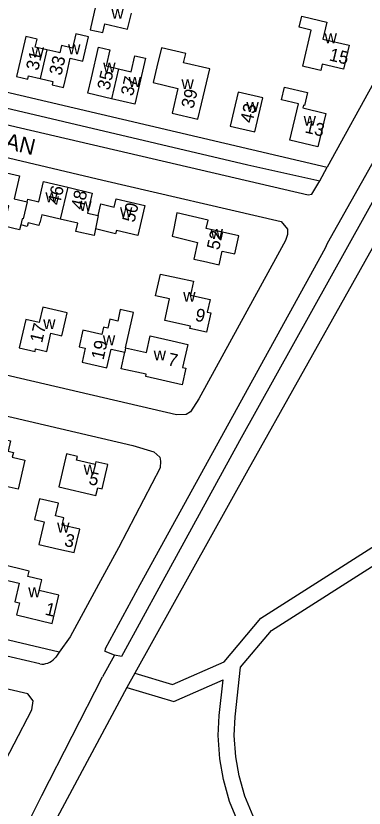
# Model space of a CAD drawing. Extents: x 161773 to 163836, y 384796 to 386521.
# Drawn here: x 162613.8 to 162722.6, y 385630.2 to 385877.5 of the extents above; entities that cross this region are included whole.
import ezdxf

# ---------------------------------------------------------------- set-up
doc = ezdxf.new("R2010")
doc.units = 0
for name, color, linetype in [('BLT_Basislijn', 7, 'Continuous'), ('BLT_Bebouwing', 7, 'Continuous'), ('BLT_Centroide', 7, 'Continuous'), ('BLT_Huisnummer', 7, 'Continuous'), ('BLT_Huisnummer_ tussenligend', 7, 'Continuous'), ('BLT_Onderverdeling_panden', 7, 'Continuous'), ('BLT_Straatnaam', 7, 'Continuous')]:
    doc.layers.add(name, color=color, linetype=linetype)

msp = doc.modelspace()

# ---------------------------------------------------------------- linework, layer by layer
at = {"layer": 'BLT_Basislijn'}
for p, q in [((162708.69, 385825.93), (162711.04, 385830.23)), ((162630.76, 385683.64), (162627.38, 385678.91)), ((162627.38, 385678.91), (162626.29, 385677.38)), ((162644.59, 385677.96), (162640.89, 385671.23)), ((162621.96, 385634.13), (162640.89, 385671.23)), ((162648.46, 385667.88), (162618.75, 385612.62)), ((162609.1, 385608.91), (162621.96, 385634.13))]:
    msp.add_line(p, q, dxfattribs=at)
for points in [[(162644.59, 385677.96), (162641.67, 385679.15), (162641.76, 385680.04), (162652.61, 385700), (162710.55, 385805.08), (162711.1, 385806.51), (162756.83, 385887.63), (162796.99, 385960.06), (162856.89, 386059.07)], [(162861.67, 386056.19), (162795.28, 385945.23), (162766.85, 385893.4), (162734.28, 385835.66), (162683.66, 385744.84), (162659.11, 385700), (162646.79, 385677.52), (162644.59, 385677.96)], [(162533.46, 385940.28), (162600, 385924.77), (162684.08, 385905.17), (162740.53, 385892.3), (162742.38, 385890.58), (162742.44, 385887.3), (162711.04, 385830.23)], [(162521.74, 385882.16), (162520.32, 385875.52), (162600, 385856.24), (162711.04, 385830.23)], [(162497.15, 385875.44), (162497.39, 385872.99), (162499.99, 385869.75), (162501.74, 385869), (162512.55, 385866.3), (162600, 385846.01), (162705.04, 385821.65), (162706.25, 385821.76), (162708.69, 385825.93)], [(162497.15, 385875.44), (162600, 385851.25), (162686.26, 385830.96), (162708.69, 385825.93)], [(162506.71, 385857.98), (162600, 385835.85), (162640.95, 385826.14), (162696.67, 385813.29), (162698.68, 385810.91), (162698.59, 385809.21), (162697.98, 385807.33), (162695.51, 385802.74), (162670.9, 385757.98), (162668.34, 385753.87), (162666.97, 385753.1), (162663.98, 385752.9), (162600, 385767.81), (162494.17, 385792.47), (162493.82, 385792.55)], [(162741.56, 385834.36), (162735.26, 385823.07), (162686.29, 385735.67), (162650.94, 385672.36)], [(162678.87, 385675.87), (162690.27, 385689.5), (162799.69, 385759.13), (162858.66, 385788.41)], [(162743.64, 385587.62), (162731.85, 385595.69), (162725.41, 385596.94), (162718, 385599.35), (162710.34, 385603.22), (162703.55, 385608.09), (162700.18, 385610.97), (162695.05, 385616.61), (162691.69, 385621.09), (162687.87, 385627.7), (162685.3, 385633.96), (162683.54, 385640.26), (162682.52, 385646.23), (162681.95, 385652.91), (162682.29, 385658.69), (162684, 385674.21), (162693.61, 385685.7), (162802.16, 385754.77), (162860.4, 385783.7)], [(162491.31, 385780.26), (162492.03, 385780.09), (162600, 385755.09), (162650.39, 385743.43), (162656.88, 385741.42), (162658.73, 385739.77), (162658.98, 385738.52), (162658.89, 385736.42), (162645.84, 385711.4), (162639.64, 385700), (162630.76, 385683.64)], [(162627.38, 385678.91), (162600, 385685.3), (162537.03, 385700), (162487.65, 385711.18), (162478.88, 385713.69)], [(162621.27, 385675.2), (162598.86, 385680.43), (162535.91, 385695.13), (162486.41, 385706.33), (162469.09, 385711.3)], [(162607.61, 385639.65), (162618.82, 385660.94), (162619.18, 385663.66), (162617.56, 385665.85), (162600, 385669.93), (162562.75, 385678.57), (162562.34, 385678.67)], [(162621.27, 385675.2), (162621.92, 385675.16), (162622.57, 385675.19), (162623.21, 385675.31), (162623.84, 385675.5), (162624.43, 385675.77), (162624.99, 385676.1), (162625.51, 385676.51), (162625.96, 385676.97), (162626.29, 385677.38)], [(162650.94, 385672.36), (162662.77, 385668.84), (162678.87, 385675.87)], [(162650.94, 385672.36), (162648.46, 385667.88)], [(162648.46, 385667.88), (162663.1, 385663.53), (162678.54, 385670.27)], [(162741.95, 385582.71), (162729.88, 385590.98), (162724.16, 385592.09), (162716.09, 385594.71), (162707.74, 385598.93), (162700.47, 385604.15), (162696.69, 385607.37), (162691.19, 385613.42), (162687.52, 385618.33), (162683.37, 385625.49), (162680.56, 385632.34), (162678.66, 385639.16), (162677.55, 385645.59), (162676.94, 385652.85), (162677.31, 385659.12), (162678.54, 385670.27)]]:
    msp.add_lwpolyline(points, dxfattribs=at)
at = {"layer": 'BLT_Bebouwing'}
for points in [[(162638.83, 385880.92), (162637.03, 385873.14)], [(162637.03, 385873.14), (162640.96, 385872.21), (162641.62, 385874.99), (162648.72, 385873.32), (162649.9, 385878.32)], [(162706.09, 385876.67), (162710.96, 385875.52), (162709.72, 385870.21), (162717.94, 385868.28), (162716.09, 385860.86), (162709.47, 385862.42), (162709, 385860.43), (162704.13, 385861.58), (162703.42, 385861.74), (162706.07, 385872.99), (162702.33, 385873.87), (162703.15, 385877.36), (162706.09, 385876.67)], [(162623.53, 385866.87), (162619.87, 385867.73), (162620.45, 385870.16), (162616.92, 385870.99), (162615.13, 385863.39), (162613.99, 385858.52), (162617.56, 385857.68), (162617.81, 385858.74), (162621.42, 385857.89)], [(162621.42, 385857.89), (162625.38, 385856.95), (162625.13, 385855.88), (162628.67, 385855.05), (162629.81, 385859.91), (162630.82, 385864.21), (162634.71, 385863.3), (162636.51, 385870.94)], [(162636.51, 385870.94), (162632.57, 385871.87), (162631.49, 385867.36), (162628.07, 385868.17), (162627.54, 385865.92), (162627.18, 385866.01), (162623.53, 385866.87)], [(162643.72, 385851.55), (162636.28, 385853.28), (162637.41, 385858.15), (162639.62, 385867.68), (162643.15, 385866.86), (162641.98, 385861.84), (162645.89, 385860.94)], [(162671.76, 385850.03), (162674.36, 385860.87), (162666.21, 385862.82), (162666.9, 385865.69), (162659.27, 385867.52), (162657.83, 385861.5), (162656.66, 385856.64), (162664.43, 385854.77), (162662.59, 385847.08), (162670.59, 385845.17), (162671.76, 385850.03)], [(162645.89, 385860.94), (162649.8, 385860.03), (162650.95, 385865), (162654.3, 385864.22), (162652.1, 385854.74), (162650.97, 385849.87), (162643.72, 385851.55)], [(162688.44, 385841.22), (162690.93, 385851.86), (162683.19, 385853.67), (162681.84, 385847.91), (162680.7, 385843.04), (162688.44, 385841.22)], [(162710.56, 385846.97), (162708.15, 385836.61), (162699.36, 385838.65), (162702.11, 385850.04), (162696.78, 385851.27), (162697.7, 385855.24), (162704.91, 385853.58), (162703.97, 385849.52), (162703.6, 385849.61), (162703.4, 385848.74), (162710.56, 385846.97)], [(162607.7, 385829.23), (162615, 385827.52), (162613.33, 385820.39), (162617.39, 385819.43)], [(162617.39, 385819.43), (162617.59, 385820.25), (162620.96, 385819.46), (162622.43, 385825.73), (162630.02, 385823.95)], [(162630.02, 385823.95), (162637.62, 385822.17), (162636.15, 385815.9), (162639.52, 385815.11)], [(162615.34, 385812.19), (162615, 385810.71), (162610.12, 385811.86), (162611.61, 385818.18), (162605.44, 385819.63)], [(162639.52, 385815.11), (162640.38, 385818.77), (162644.49, 385817.8), (162645.1, 385820.39), (162654.09, 385818.28), (162652.95, 385813.41), (162651.88, 385808.89), (162645.19, 385810.46), (162644.96, 385809.48), (162638.7, 385810.94)], [(162669.35, 385801.57), (162672.41, 385800.87), (162677.28, 385799.77), (162678.25, 385804.05), (162682.15, 385803.16), (162683.43, 385808.79), (162673.25, 385811.1), (162673.85, 385813.74), (162664.1, 385815.95), (162663.12, 385811.05), (162662.64, 385808.68), (162670.52, 385806.76), (162669.35, 385801.57)], [(162627.69, 385814.01), (162621.9, 385815.37), (162621.31, 385812.86), (162621.16, 385812.9), (162620.96, 385812.08), (162617.65, 385812.86), (162617.38, 385811.71), (162615.34, 385812.19)], [(162638.7, 385810.94), (162638.22, 385808.88), (162632.54, 385810.21), (162633.14, 385812.73), (162627.69, 385814.01)], [(162664.38, 385795.67), (162669.27, 385794.61), (162668.33, 385790.34), (162674.47, 385788.99), (162673.59, 385785), (162674.68, 385784.76), (162673.35, 385778.71), (162668.16, 385779.87), (162668.32, 385780.64), (162660.32, 385782.41), (162661.81, 385789.16), (162657.44, 385790.12), (162658.93, 385796.89), (162664.38, 385795.67)], [(162629.28, 385782.49), (162629.8, 385784.78), (162622.2, 385786.53), (162621.1, 385781.75), (162616.92, 385782.71), (162616.01, 385778.74), (162614.89, 385773.86), (162619.79, 385772.74), (162619.97, 385773.52), (162623.44, 385772.72), (162624.75, 385778.4), (162628.16, 385777.62), (162629.28, 385782.49)], [(162648.08, 385773.82), (162650.56, 385784.86), (162646.42, 385785.79), (162645.61, 385782.22), (162643.18, 385782.76), (162642.57, 385780.04), (162641.16, 385780.35), (162640.64, 385778.02), (162634.73, 385779.35), (162633.57, 385774.17), (162635.47, 385773.74), (162634.48, 385769.34), (162642.21, 385767.61), (162643.53, 385773.46), (162647.86, 385772.49)], [(162648.08, 385773.82), (162654.57, 385772.36), (162655.76, 385777.6), (162662.65, 385776.04), (162667.53, 385774.93), (162665.89, 385767.7), (162666.91, 385767.47), (162665.73, 385762.29), (162654.35, 385764.87), (162654.52, 385765.62), (162646.7, 385767.32), (162647.86, 385772.49)], [(162604.82, 385746.48), (162612.13, 385744.8), (162611.39, 385741.6), (162613.03, 385741.23), (162612.69, 385739.76), (162616.63, 385738.85), (162614.52, 385729.71), (162608.87, 385731.02), (162609.8, 385734.73), (162602.5, 385736.42)], [(162633.04, 385739.96), (162629.64, 385740.74), (162627.26, 385730.47), (162638.81, 385727.79), (162639.37, 385730.19), (162640.8, 385729.86), (162642.56, 385737.44), (162638.77, 385738.32), (162638.56, 385737.44), (162632.77, 385738.78), (162633.04, 385739.96)], [(162627.18, 385711.07), (162632.05, 385709.94), (162633.75, 385717.25), (162628.28, 385718.52), (162628.81, 385720.78), (162626.19, 385721.39), (162627.12, 385725.35), (162621.17, 385726.74), (162619.68, 385720.3), (162622.64, 385719.61), (162620.99, 385712.51), (162627.18, 385711.07)], [(162621.1, 385698.16), (162621.89, 385701.47), (162617.58, 385702.5), (162617.98, 385704.2), (162609.15, 385706.31), (162608.11, 385701.96), (162614.84, 385700.41), (162613.51, 385694.63), (162614.9, 385694.31), (162613.96, 385690.49), (162625.12, 385687.84), (162627.23, 385696.7), (162621.1, 385698.16)]]:
    msp.add_lwpolyline(points, dxfattribs=at)
at = {"layer": 'BLT_Onderverdeling_panden'}
for p, q in [((162623.53, 385866.87), (162621.42, 385857.89)), ((162645.89, 385860.94), (162643.72, 385851.55)), ((162630.02, 385823.95), (162627.69, 385814.01)), ((162639.52, 385815.11), (162638.7, 385810.94)), ((162648.08, 385773.82), (162647.86, 385772.49))]:
    msp.add_line(p, q, dxfattribs=at)
msp.add_lwpolyline([(162617.39, 385819.43), (162616.14, 385814.07), (162615.8, 385814.15), (162615.34, 385812.19)], dxfattribs=at)

# ---------------------------------------------------------------- texts
at = {"layer": 'BLT_Centroide'}
for p in [(162643.65, 385876.56), (162710.21, 385868.91), (162630.12, 385865.44), (162618.75, 385864.53), (162641.09, 385859.75), (162649.02, 385855.28), (162665.52, 385854.59), (162685.81, 385847.45), (162703.67, 385843.17), (162623.06, 385819.28), (162633.61, 385816.55), (162646.33, 385814.66), (162674.61, 385807.84), (162666.06, 385788.23), (162622.34, 385779.73), (162640.97, 385774.66), (162656.84, 385769.94), (162634.98, 385734.28), (162626.7, 385716.23), (162617.67, 385696.05)]:
    msp.add_text('w', height=4, dxfattribs=at).set_placement(p)
at = {"layer": 'BLT_Huisnummer'}
for s, rotation, p in [('31', 76.7773, (162620.77, 385860.18)), ('15', 346.7682, (162711.41, 385863.58)), ('33', 76.7752, (162628, 385858.65)), ('35', 76.955, (162643, 385854.05)), ('37', 76.9504, (162650.37, 385852.23)), ('39', 76.5279, (162669.25, 385848.3)), ('43', 76.8289, (162687.66, 385843.78)), ('13', 346.9431, (162703.84, 385841.09)), ('46', 76.791, (162627.52, 385818.15)), ('50', 76.787, (162650.83, 385812.77)), ('52', 77.2213, (162677.26, 385804.19)), ('9', 347.5424, (162669.55, 385782.37)), ('17', 77.0385, (162622, 385775.2)), ('19', 77.3231, (162641.17, 385769.9)), ('7', 347.2166, (162660.97, 385768.49)), ('5', 346.9435, (162636.32, 385731.37)), ('3', 346.9061, (162628.73, 385712.1)), ('1', 346.6008, (162622.69, 385690.63))]:
    msp.add_text(s, height=4, rotation=rotation, dxfattribs=at).set_placement(p)
at = {"layer": 'BLT_Huisnummer_ tussenligend'}
msp.add_text('48', height=4, rotation=76.7926, dxfattribs=at).set_placement((162634.81, 385816.73))
at = {"layer": 'BLT_Straatnaam'}
msp.add_text('ICARUSLAAN', height=5, rotation=346.5043, dxfattribs=at).set_placement((162577.62, 385843.91))

doc.saveas('drawing.dxf')
